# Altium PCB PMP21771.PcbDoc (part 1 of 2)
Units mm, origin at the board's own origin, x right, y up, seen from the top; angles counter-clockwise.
Board outline 125.73 x 87.63 mm, 4 copper layers (Top Layer, Signal Layer 1, Signal Layer 2, Bottom Layer), stack 2.225 mm thick; 58 components, 23 nets, 122 pads, 58 vias.
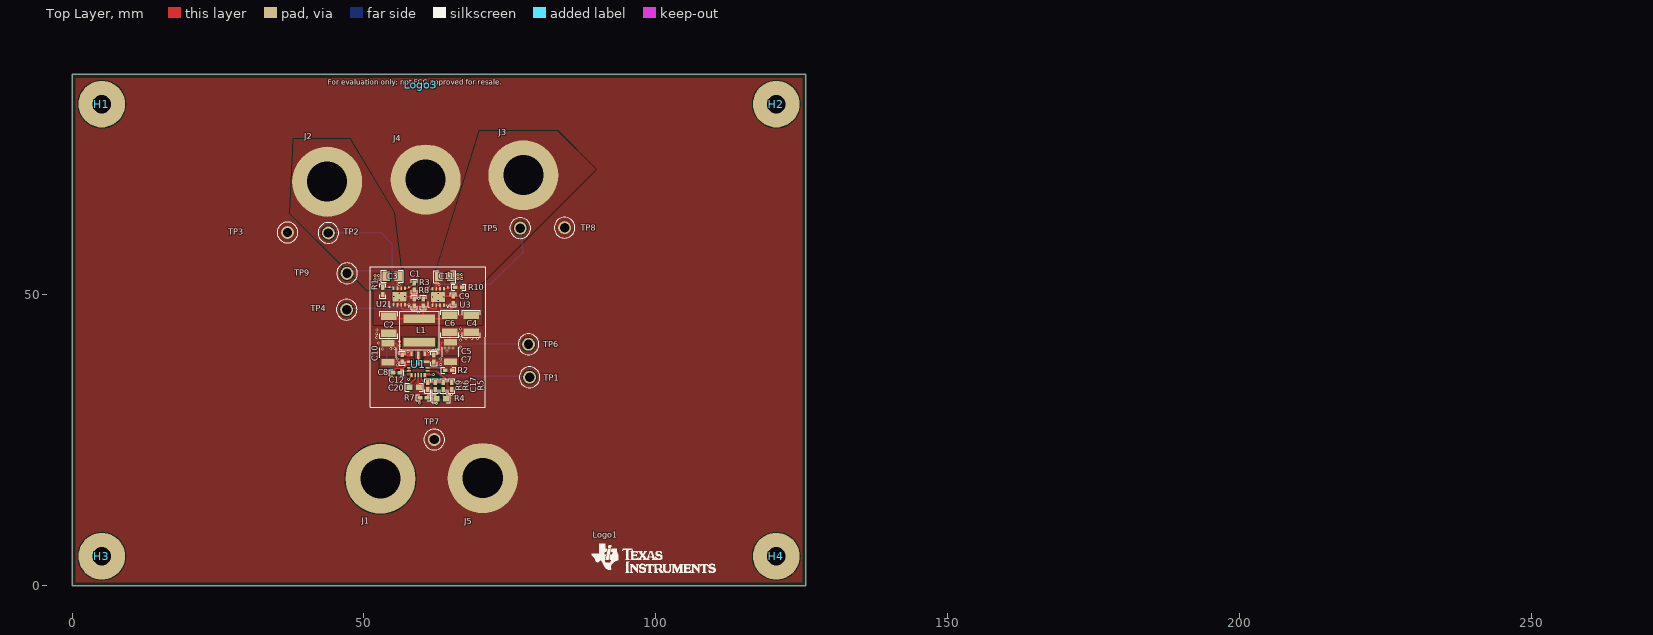
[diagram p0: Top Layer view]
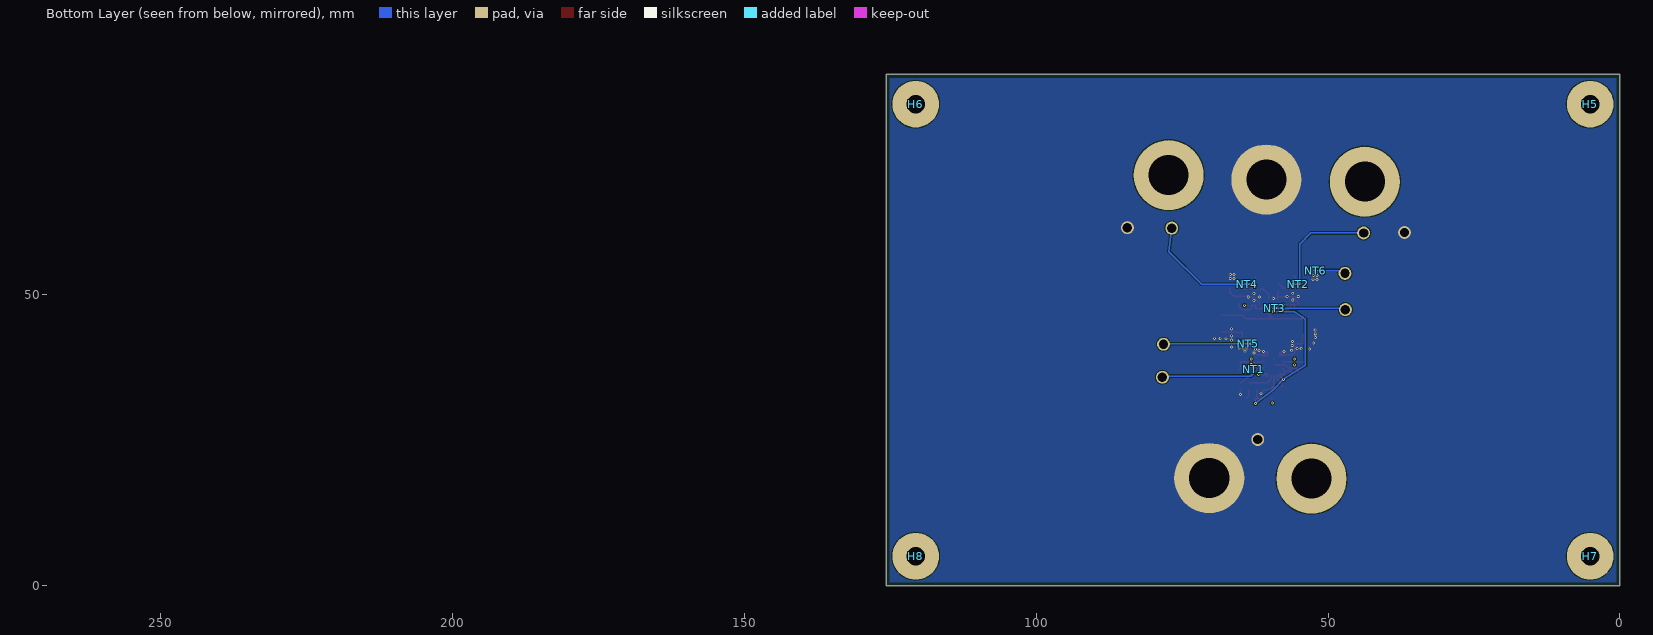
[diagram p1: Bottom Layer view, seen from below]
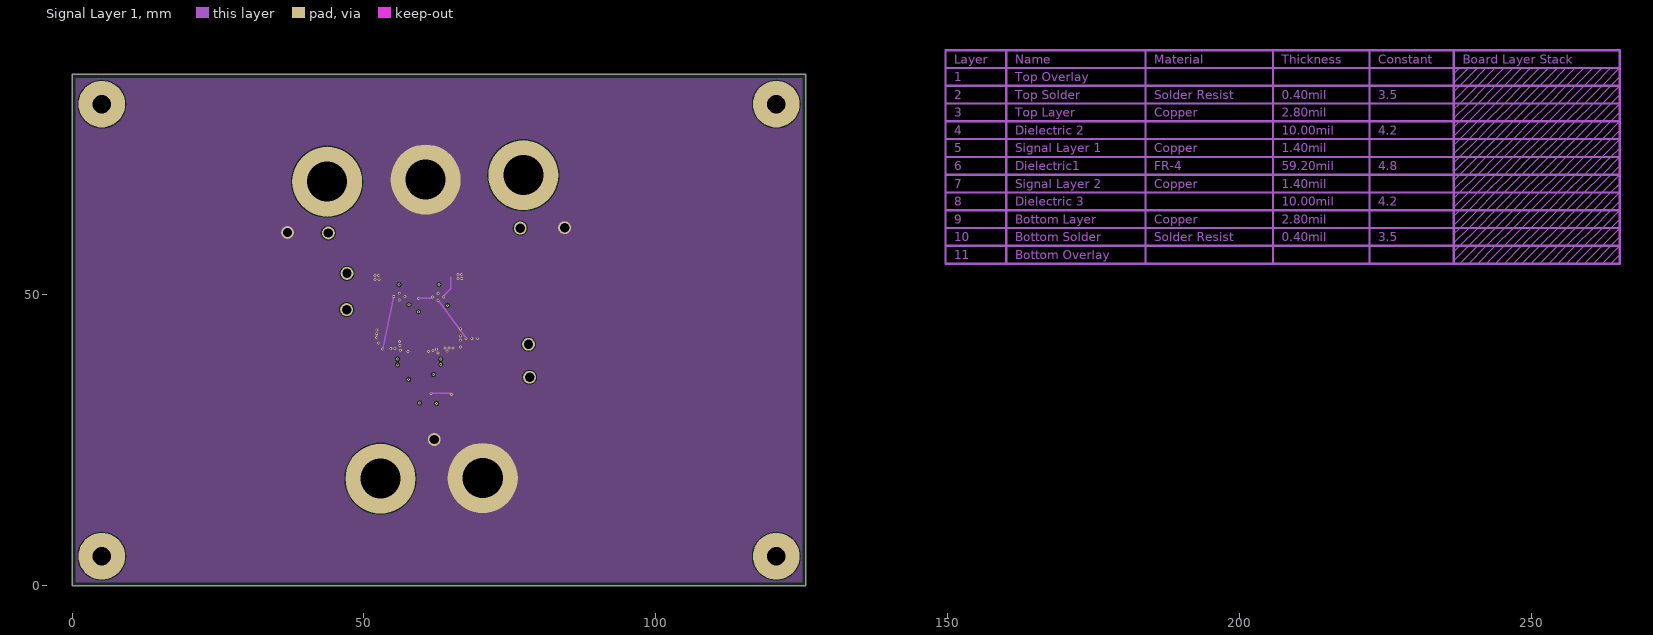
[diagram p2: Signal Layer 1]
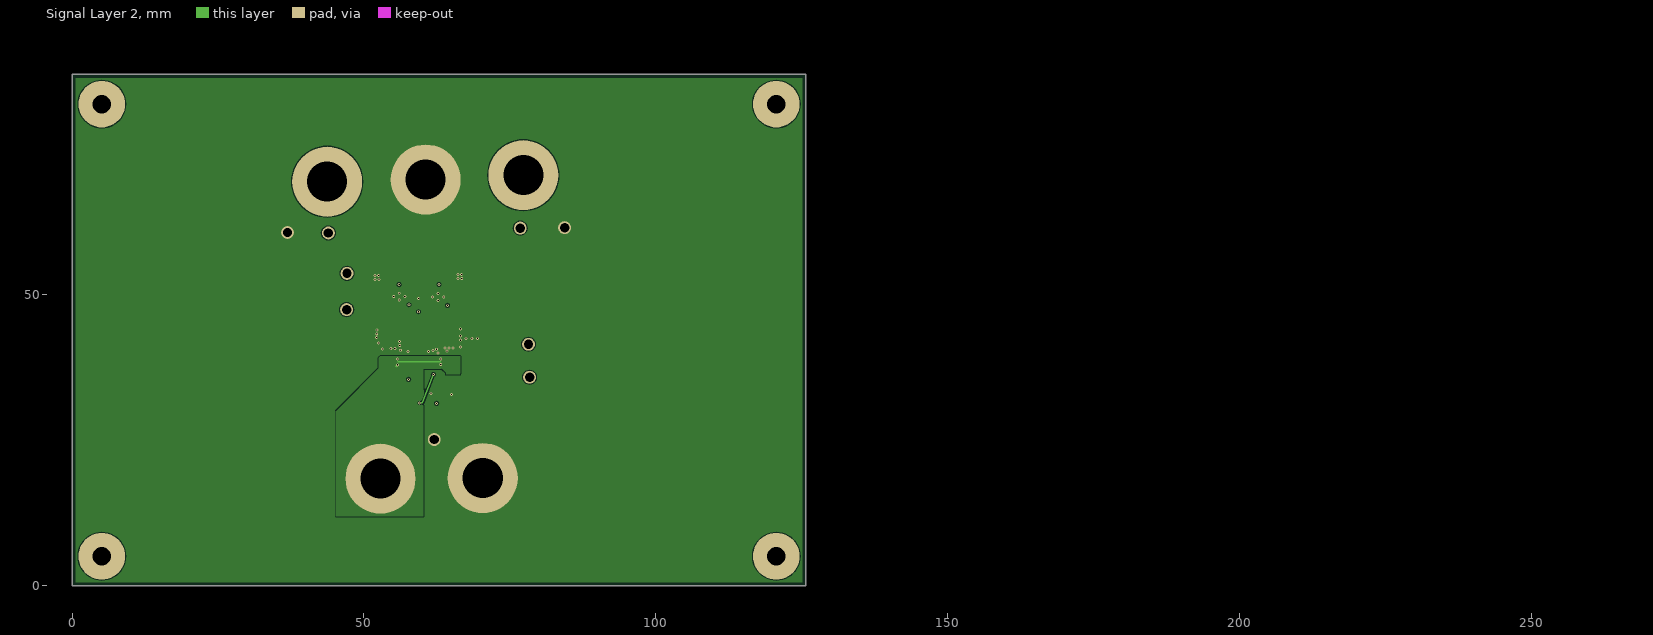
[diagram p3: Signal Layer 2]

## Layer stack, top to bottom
Top Solder: solder mask 0.0102, Solder Resist, Dk 3.5
Top Layer: signal copper 0.0711
Dielectric 2: dielectric 0.254, Dk 4.2
Signal Layer 1: signal copper 0.0356
Dielectric1: core 1.5037, FR-4, Dk 4.8
Signal Layer 2: signal copper 0.0356
Dielectric 3: dielectric 0.254, Dk 4.2
Bottom Layer: signal copper 0.0711
Bottom Solder: solder mask 0.0102, Solder Resist, Dk 3.5

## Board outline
0,0 125.73,0 125.73,87.63 0,87.63

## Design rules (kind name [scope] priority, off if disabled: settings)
AcuteAngle [All] p1: minimum=4.50000000000000E+0001 checktracksonly=FALSE
AssemblyTestPointUsage [All] p1: valid=2
BoardOutlineClearance BoardOutlineClearance_MountingHoles [OnCopper and InComponentClass('Mounting Holes')] p1: gap=0.635 ignorepadtopadclearanceinfootprint=FALSE
BoardOutlineClearance BoardOutlineClearance_Poly [OnCopper and InPoly] p2: gap=0.635 ignorepadtopadclearanceinfootprint=FALSE
BoardOutlineClearance [OnCopper and Not InComponentClass('Logo') and not InComponentClass('FiducialMark') and not InRegion(1000,500,4000,800)] p3: gap=0.635 ignorepadtopadclearanceinfootprint=FALSE
Clearance Clearance_Keepouts [((IsTrack Or IsArc) And Not InPoly) And IsFree and IsKeepOut vs ((IsTrack Or IsArc) And Not InPoly) And IsFree and IsKeepOut] p1: gap=0 ignorepadtopadclearanceinfootprint=FALSE
Clearance Clearance_Poly [InPolygon] p2: gap=0.152 ignorepadtopadclearanceinfootprint=FALSE
Clearance [All] p3: gap=0.2 ignorepadtopadclearanceinfootprint=FALSE except(0: Arc-Hole Track-Hole SMDPad-Hole THPad-Hole Via-Hole Fill-Hole Poly-Hole Region-Hole Text-Hole)
ComponentClearance ComponentClearance_MountingHoles_FiducialMarks [InComponentClass('Mounting Holes') vs InComponentClass('FiducialMark')] p1: gap=1.27 collisioncheckmode=3 verticalgap=0.254 showdistances=FALSE
ComponentClearance ComponentClearance_Shunt [InComponentClass('Header') vs InComponentClass('Shunt')] p2: gap=0 collisioncheckmode=3 verticalgap=0 showdistances=FALSE
ComponentClearance ComponentClearance_Logo [InComponentClass('Logo')] p3: gap=1.27 collisioncheckmode=3 verticalgap=0.254 showdistances=FALSE
ComponentClearance ComponentClearance_ScrewToNut [(HasFootprint('NY PMS 440 0025 PH')) vs (HasFootprint('Keystone_1902C'))] p4: gap=0.127 collisioncheckmode=3 verticalgap=0.254 showdistances=FALSE
ComponentClearance ComponentClearance_MountingHoles [InComponentClass('Mounting Holes')] p5: gap=6.35 collisioncheckmode=3 verticalgap=2540 showdistances=FALSE
ComponentClearance ComponentClearance_SmallPassives [HasFootprint('0201*') or HasFootprint('0402*') or HasFootprint('0508') or HasFootprint('0603*') or HasFootprint('0612') or HasFootprint('0805*') or HasFootprint('0815*') or HasFootprint('0830*') or HasFootprint('1206*') or HasFootprint('1210*') or HasFootprint('1808*') or HasFootprint('1812*') or HasFootprint('1825*') or HasFootprint('2010*') or HasFootprint('2220*') or HasFootprint('2225*') or HasFootprint('2512*') or HasFootprint('2728*') or HasFootprint('3518*') vs HasFootprint('0201*') or HasFootprint('0402*') or HasFootprint('0508') or HasFootprint('0603*') or HasFootprint('0612') or HasFootprint('0805*') or HasFootprint('0815*') or HasFootprint('0830*') or HasFootprint('1206*') or HasFootprint('1210*') or HasFootprint('1808*') or HasFootprint('1812*') or HasFootprint('1825*') or HasFootprint('2010*') or HasFootprint('2220*') or HasFootprint('2225*') or HasFootprint('2512*') or HasFootprint('2728*') or HasFootprint('3518*')] p6: gap=0.1 collisioncheckmode=3 verticalgap=0.254 showdistances=FALSE
ComponentClearance ComponentClearance_THtoSMT [IsThruComponent vs IsSMTComponent] p7: gap=0.381 collisioncheckmode=3 verticalgap=0.762 showdistances=FALSE
ComponentClearance ComponentClearance_THtoTH [IsThruComponent vs IsThruComponent] p8: gap=0.381 collisioncheckmode=3 verticalgap=0.762 showdistances=FALSE
ComponentClearance [All] p9: gap=0.1 collisioncheckmode=3 verticalgap=0.1 showdistances=FALSE
DiffPairsRouting [All] p1: maxlimit=2.54 minlimit=0.254 mostfreqgap=0.254 toplayer_minwidth=0.381 toplayer_maxwidth=0.381 toplayer_prefwidth=0.381 midlayer1_minwidth=0.381 midlayer1_maxwidth=0.381 midlayer1_prefwidth=0.381 midlayer2_minwidth=0.381 midlayer2_maxwidth=0.381 midlayer2_prefwidth=0.381 bottomlayer_minwidth=0.381 bottomlayer_maxwidth=0.381 bottomlayer_prefwidth=0.381 maxuncoupledlength=25.4
FabricationTestPointUsage TestPointUsage [All] p1: valid=2 allowmultiple=FALSE
FabricationTestpoint Testpoint [All] p1: side=3 testpointundercomponent=TRUE minsize=1.016 maxsize=2.54 preferedsize=1.524 minholesize=0 maxholesize=1.016 preferedholesize=0.813 testpointgrid=0.025 allowsidetop=TRUE allowsidebottom=TRUE usegrid=TRUE gridtolerance=0
FanoutControl Fanout_LCC [IsLCC] p1: bgadir=Out bgaviamode=Centered fanoutstyle=Auto fanoutdirection=Alternating viagrid=0.025 // Fanout_LCC (Default Rule)
FanoutControl Fanout_BGA [IsBGA] p2: bgadir=Out bgaviamode=Centered fanoutstyle=Auto fanoutdirection=Alternating viagrid=0.025 // Fanout_BGA (Default Rule)
FanoutControl Fanout_Default [All] p4: bgadir=Out bgaviamode=Centered fanoutstyle=Auto fanoutdirection=Alternating viagrid=0.025 // Fanout_Default (Default Rule)
FanoutControl Fanout_Small [(CompPinCount < 5)] p5: bgadir=Out bgaviamode=Centered fanoutstyle=Auto fanoutdirection=OutThenIn viagrid=0.025 // Fanout_Small (Default Rule)
HoleSize [All] p1: absolutevalues=TRUE maxlimit=6.375 minlimit=0.2 maxpercent=80.000 minpercent=20.000
MinimumAnnularRing MinimumAnnularRing_ThermalPadVias [IsVia and InAnyComponent] p1: minimumring=0.15
MinimumAnnularRing [All] p2: minimumring=0.203
MinimumSolderMaskSliver MinimumSolderMaskSliver_Logo [InComponentClass('Logo') vs InComponentClass('Logo')] p1: minsoldermaskwidth=0.018
MinimumSolderMaskSliver [All] p2: minsoldermaskwidth=0.1
PlaneConnect [All] p1: planeconnectstyle=Direct reliefexpansion=0.254 reliefentries=4 reliefconductorwidth=0.254 reliefairgap=0.254
PolygonConnect [All] p1: connectstyle=Direct reliefconductorwidth=0.254 reliefentries=4 polygonreliefangle="90 Angle" airgapwidth=0.254
RoutingLayers [All] p1: top layer_v5=TRUE mid layer 1_v5=FALSE mid layer 2_v5=FALSE bottom layer_v5=TRUE
RoutingVias ThermalPadVias [IsVia and InAnyComponent] p1: holewidth=0.2 width=0.5 viastyle="Through Hole" minholewidth=0.2 minwidth=0.5 maxholewidth=0.33 maxwidth=0.6
RoutingVias [All] p2: holewidth=0.406 width=0.864 viastyle="Through Hole" minholewidth=0.2 minwidth=0.66 maxholewidth=1.016 maxwidth=1.651
SilkToBoardRegionClearance [Not ((IsComment or IsDesignator) And (Hide <> 'False')) and not InRegion(1000,500,4000,800)] p1:
SilkToSilkClearance SilkToSilkClearance_Pb-FreeLogo [(HasFootprint('Pb-Free_Overlay_Medium') OR HasFootprint('Pb-Free_Overlay_Small')) vs (HasFootprint('Pb-Free_Overlay_Medium') OR HasFootprint('Pb-Free_Overlay_Small'))] p1: silktosilkclearance=0
SilkToSilkClearance [All] p2: silktosilkclearance=0.102
SilkToSolderMaskClearance SilkToComponentPadClearance [IsPad and InAnycomponent] p1: minsilkscreentomaskgap=0.127 clearancetoexposedcopper=TRUE
SilkToSolderMaskClearance "Silk to Solder Mask Opening" [All] p2: minsilkscreentomaskgap=0.102 clearancetoexposedcopper=FALSE
SolderMaskExpansion [All] p1: expansion=0.05
Width [All] p1: maxlimit=2.54 minlimit=0.152 preferedwidth=0.254 checkconnectedcopper=TRUE
14 further rules are at their usual default settings.

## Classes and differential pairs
component class PMP21771_Main: C1 C2 C3 C4 C5 C6 C7 C8 C9 C10 C11 C12 C17 C20 J1 J2 J3 J4 J5 L1 NT1 NT2 NT3 NT4 NT5 NT6 R1 R2 R3 R4 R5 R6 R7 R8 R9 R10 TP1 TP2 TP3 TP4 TP5 TP6 TP7 TP8 TP9 U1 U2 U3
component class "Mounting Holes": H1 H2 H3 H4
component class Logo: Logo1
component class PMP21771_Hardware: H1 H2 H3 H4 H5 H6 H7 H8 Logo1 Logo3

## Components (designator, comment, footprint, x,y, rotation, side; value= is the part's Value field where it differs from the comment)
C1 "C0402C104K4RACAUTO" 0402 58.598,48.555 r90 top value=0.1uF
C2 "GCM32ER70J476KE19L" 1210_270 54.25,44.724 r270 top value=47uF
C3 "JMJ212CB7106KGHT" 0805_HV 54.824,53.042 r180 top value=10uF
C4 "GCM32ER70J476KE19L" 1210_270 68.395,44.928 r270 top value=47uF
C5 "CGA6P3X7R1H475K250AB" 1210_280 64.826,40.075 r90 top value=4.7uF
C6 "GCM32ER70J476KE19L" 1210_270 64.702,44.928 r270 top value=47uF
C7 "CGA2B3X7R1H104K050BB" 0402 61.996,38.965 r90 top value=0.1uF
C8 "CGA2B3X7R1H104K050BB" 0402 56.576,39 r90 top value=0.1uF
C9 "C0402C104K4RACAUTO" 0402 65.33,49.021 r90 top value=0.1uF
C10 "CGA6P3X7R1H475K250AB" 1210_280 54.126,39.95 r90 top value=4.7uF
C11 "JMJ212CB7106KGHT" 0805_HV 63.825,53 r0 top value=10uF
C12 "C0402C104K4RACAUTO" 0402 55.575,36.55 r180 top value=0.1uF
C17 "C0402C330J5GACAUTO" 0402 63.559,34.25 r90 top value=33pF
C20 "GCM188R71C105KA64D" 0603 58.598,34.026 r0 top value=1uF
H1 "NY PMS 440 0025 PH" "NY PMS 440 0025 PH" 5.08,82.55 r0 top locked
H2 "NY PMS 440 0025 PH" "NY PMS 440 0025 PH" 120.65,82.55 r0 top locked
H3 "NY PMS 440 0025 PH" "NY PMS 440 0025 PH" 5.08,5.08 r0 top locked
H4 "NY PMS 440 0025 PH" "NY PMS 440 0025 PH" 120.65,5.08 r0 top locked
H5 "1902C" Keystone_1902C 5.08,82.55 r180 bottom locked
H6 "1902C" Keystone_1902C 120.65,82.55 r180 bottom locked
H7 "1902C" Keystone_1902C 5.08,5.08 r180 bottom locked
H8 "1902C" Keystone_1902C 120.65,5.08 r180 bottom locked
J1 "3267" Pomona_3267 52.825,18.375 r0 top
J2 "3267" Pomona_3267 43.7,69.25 r0 top
J3 "3267" Pomona_3267 77.3,70.375 r0 top
J4 "3267" Pomona_3267 60.578,69.625 r0 top
J5 "3267" Pomona_3267 70.35,18.475 r0 top
L1 "XAL6060-472MEB" XAL6060 59.476,43.777 r90 top value=4.7uH
Logo1 "Texas Instruments" TI_Stacked_Overlay_Small 99.623,4.75 r0 top
Logo3 "FCC disclaimer" FCC_disclaimer 59.69,85.852 r0 top
NT1 "Net-Tie" Net-Tie_10mil 62.715,37.146 r90 bottom net-tie
NT2 "Net-Tie" Net-Tie_10mil 55.082,51.65 r180 bottom net-tie
NT3 "Net-Tie" Net-Tie_10mil 59.146,47.575 r180 bottom net-tie
NT4 "Net-Tie" Net-Tie_10mil 63.869,51.675 r0 bottom net-tie
NT5 "Net-Tie" Net-Tie_10mil 63.663,41.5 r180 bottom net-tie
NT6 "Net-Tie" Net-Tie_10mil 52.139,54.04 r180 bottom net-tie
R1 "ERJ-2RKF1003X" 0402 53.23,50.529 r270 top value=100k
R2 "CRCW040244K2FKED" 0402 64.5,36.925 r0 top value=44.2k
R3 "CRCW040230K1FKED" 0402 58.58,51.287 r90 top value=30.1k
R4 "CRCW06031K00FKEA" 0603 63.243,32.062 r180 top value=1.00k
R5 "CRCW040239K2FKED" 0402 65,34.25 r90 top value=39.2k
R6 "RMCF0402FT100K" 0402 62.24,34.25 r270 top value=100k
R7 "CRCW040240R2FKED" 0402 60.2,32.232 r0 top value=40.2
R8 "ERJ-2RKF1003X" 0402 60.18,48.555 r270 top value=100k
R9 "CRCW040224K9FKED" 0402 60.92,34.25 r90 top value=24.9k
R10 "CRCW040230K1FKED" 0402 66.229,51.185 r180 top value=30.1k
TP1 "5129" Keystone5129 78.375,35.75 r0 top
TP2 "5129" Keystone5129 43.9,60.475 r0 top
TP3 "5011" Keystone5011 36.893,60.55 r0 top
TP4 "5129" Keystone5129 47.025,47.335 r0 top
TP5 "5129" Keystone5129 76.775,61.3 r0 top
TP6 "5129" Keystone5129 78.2,41.4 r0 top
TP7 "5011" Keystone5011 62.039,25.075 r0 top
TP8 "5011" Keystone5011 84.375,61.375 r0 top
TP9 "5011" Keystone5011 47.1,53.55 r0 top
U1 "LM61460AANQRJRTQ1" RJR0014A 59.286,37.965 r90 top
U2 "TPS2557QDRBRQ1" DRB0008B 56.046,49.571 r90 top
U3 "TPS2557QDRBRQ1" DRB0008B 62.715,49.5 r90 top

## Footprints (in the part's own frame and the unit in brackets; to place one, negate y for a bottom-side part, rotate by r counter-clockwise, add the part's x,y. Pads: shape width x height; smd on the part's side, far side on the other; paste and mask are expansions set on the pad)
0402 [mm] "0402 from SM-752 data"
  rect 0.8x0.6 smd: 1(-0.6,0) 2(0.6,0)
  silkscreen extent -1.22,-0.52 1.22,0.52, body extent -0.55,-0.3 0.55,0.3, height 0.6
0603 [mm] "0603 from SM-752 data"
  rect 1x0.95 smd: 1(-0.8,0) 2(0.8,0)
  silkscreen extent -1.52,-0.69 1.52,0.69, body extent -0.87,-0.47 0.87,0.47, height 1
0805_HV [mil] "0805 with 30mil clearance between pads"
  rect 50x63 smd: 1(-40,0) 2(40,0)
  silkscreen extent -74,-40 74,40, body extent -43,-29 43,29, height 57
1210_270 [mm] "1210"
  rect 1.3x2.7 smd: 1(-1.45,0) 2(1.45,0)
  silkscreen extent -2.32,-1.57 2.32,1.57, body extent -1.7,-1.35 1.7,1.35, height 2.7
1210_280 [mm] "SMD, 2-Leads, Body 3.6x2.8mm, Height 2.8mm"
  rect 1.1x2.2 smd: 1(-1.65,0) 2(1.65,0)
  silkscreen extent -0.84,-1.4 0.84,1.4, body extent -1.8,-1.4 1.8,1.4, height 2.8
DRB0008B [mm] "SON, 8-Leads, Body 3x3mm, Pitch 0.65mm, Thermal Pad 2.4x1.65mm, TI Recommended"
  rrect33% 0.6x0.3 smd: 1(-1.4,0.975) 2(-1.4,0.325) 3(-1.4,-0.325) 4(-1.4,-0.975) 5(1.4,-0.975) 6(1.4,-0.325) 7(1.4,0.325) 8(1.4,0.975)
  rrect9% 1.47x1.06 on Top Paste: 9(0,0.63) 9(0,-0.63)
  rrect6% 1.65x2.4 smd paste-1.2: 9(0,0)
  silkscreen extent -1.73,-1.73 1.73,1.73, body extent -1.5,-1.5 1.5,1.5, height 0.96
FCC_disclaimer [mm]
Keystone5011 [mil] "Keystone Multipurpose loops"
  round 87 hole 63: 1(0,0)
  silkscreen extent -70,-70 70,70, body extent -63,-63 63,62, height 319
Keystone5129 [mil] "Keystone Multipurpose loops"
  round 87 hole 63: 1(0,0)
  silkscreen extent -70,-70 70,70, body extent -63,-63 63,62, height 319
Keystone_1902C [mil] "Hex Standoff, 4-40 threaded, nylon"
  round 1 on Mech4: 0(0,0)
  body extent -145,-126 146,126, height 501
Net-Tie_10mil [mil] "10mil net tie, no solder mask opening, no solder paste"
  rect 10x10 smd paste-5 mask-5: 1(-10,0) 2(10,0)
  Top Layer region: -6,5 6,5 6,-5 -6,-5
"NY PMS 440 0025 PH" [mm] "4-40 nylon screw and mounting hole"
  round 8 hole 3.2: 1(0,0)
  body extent -3.3,-3.3 3.3,3.3, height 2.69
Pomona_3267 [mm] "Standard Uninsulated Banana Jack"
  round 12 hole 6.858: 1(0,0)
  body extent -4.12,-4.82 4.26,4.85, height 2.79
RJR0014A [mm] "VQFN-HR-14"
  rrect25% 0.7x0.4 smd paste-0.3: 1(-1.85,1.15) 5(-1.85,-1.15)
  rrect40% 0.7x0.25 smd: 2(-1.85,0.525) 4(-1.85,-0.525)
  rrect33% 0.7x0.3 smd: 3(-1.85,0)
  rrect40% 0.25x0.7 smd: 6(-1.125,-1.6) 7(-0.625,-1.6) 13(-0.625,1.6) 14(-1.125,1.6)
  rrect25% 0.4x1 smd: 8(0.45,-1.45) 12(0.45,1.45)
  rrect25% 0.8x0.4 smd paste-0.3: 9(1.8,-1.15) 11(1.8,1.15)
  rrect25% 1.1x0.4 on Top Paste: 10(0.35,0) 10(1.65,0)
  rrect25% 2.4x0.4 smd paste-0.3: 10(1,0)
  Top Layer region: -2.2,1 -2.2,1.3 -2.196,1.319 -2.185,1.335 -2.169,1.346 -2.15,1.35 -2.15,1.35 -2.15,1.35 -1.97,1.35 -1.924,1.359 -1.885,1.385 -1.859,1.424 -1.85,1.47 -1.85,1.47 -1.85,1.9 -1.85,1.9 -1.846,1.919 -1.835,1.935 -1.819,1.946 -1.8,1.95 -1.8,1.95 -1.55,1.95 -1.531,1.946 -1.515,1.935 -1.504,1.919 -1.5,1.9 -1.5,1.9 -1.5,1 -1.504,0.981 -1.515,0.965 -1.531,0.954 -1.55,0.95 -1.55,0.95 -2.15,0.95 -2.169,0.954 -2.185,0.965 -2.196,0.981 -2.2,1
  Top Layer region: 1.4,1 1.4,1.9 1.404,1.919 1.415,1.935 1.431,1.946 1.45,1.95 1.45,1.95 1.75,1.95 1.769,1.946 1.785,1.935 1.796,1.919 1.8,1.9 1.8,1.9 1.8,1.47 1.809,1.424 1.835,1.385 1.874,1.359 1.92,1.35 1.92,1.35 2.15,1.35 2.15,1.35 2.169,1.346 2.185,1.335 2.196,1.319 2.2,1.3 2.2,1.3 2.2,1 2.196,0.981 2.185,0.965 2.169,0.954 2.15,0.95 2.15,0.95 1.45,0.95 1.431,0.954 1.415,0.965 1.404,0.981 1.4,1
  Top Layer region: 1.4,-1.9 1.404,-1.919 1.415,-1.935 1.431,-1.946 1.45,-1.95 1.45,-1.95 1.75,-1.95 1.769,-1.946 1.785,-1.935 1.796,-1.919 1.8,-1.9 1.8,-1.9 1.8,-1.47 1.809,-1.424 1.835,-1.385 1.874,-1.359 1.92,-1.35 1.92,-1.35 2.15,-1.35 2.169,-1.346 2.185,-1.335 2.196,-1.319 2.2,-1.3 2.2,-1.3 2.2,-1 2.196,-0.981 2.185,-0.965 2.169,-0.954 2.15,-0.95 2.15,-0.95 1.45,-0.95 1.431,-0.954 1.415,-0.965 1.404,-0.981 1.4,-1 1.4,-1
  Top Layer region: -2.15,-1.35 -2.169,-1.346 -2.185,-1.335 -2.196,-1.319 -2.2,-1.3 -2.2,-1.3 -2.2,-1 -2.196,-0.981 -2.185,-0.965 -2.169,-0.954 -2.15,-0.95 -2.15,-0.95 -1.55,-0.95 -1.531,-0.954 -1.515,-0.965 -1.504,-0.981 -1.5,-1 -1.5,-1 -1.5,-1.9 -1.504,-1.919 -1.515,-1.935 -1.531,-1.946 -1.55,-1.95 -1.55,-1.95 -1.8,-1.95 -1.819,-1.946 -1.835,-1.935 -1.846,-1.919 -1.85,-1.9 -1.85,-1.9 -1.85,-1.9 -1.85,-1.47 -1.859,-1.424 -1.885,-1.385 -1.924,-1.359 -1.97,-1.35 -1.97,-1.35
  body extent -2,-1.75 2,1.75, height 1
TI_Stacked_Overlay_Small [mm]
  silkscreen extent -10.63,-2.49 10.63,2.49
XAL6060 [mil] "Coilcraft recommended land pattern Document 887-4 Revised 11/20/12"
  rect 56x210 smd: 1(-79.5,0) 2(79.5,0)
  silkscreen extent -129,-133 129,133, body extent -129,-133 129,133, height 240

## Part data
C1 C9: library part CMP-0006237-2, "CAP, CERM, 0.1 uF, 16 V, +/- 10%, X7R, AEC-Q200 Grade 1, 0402", Cap_Case=0402, Manufacturer=Kemet, Supplier Part Number 1=399-6828-1-ND, TempCo=X7R, Tolerance_%=10%, Value1=Unknown, Value2=16V, ValueDisplayed=0.1uF
C2 C4 C6: library part CMP-0009172-1, "CAP, CERM, 47 uF, 6.3 V, +/- 10%, X7R, AEC-Q200 Grade 1, 1210", Cap_Case=1210, Manufacturer=MuRata, Supplier Part Number 1=490-4844-1-ND, TempCo=X7R, Tolerance_%=10%, Value1=Unknown, Value2=6.3V, ValueDisplayed=47uF
C3 C11: library part CMP-0081188-1, "CAP, CERM, 10 µF, 6.3 V,+/- 10%, X7R, AEC-Q200 Grade 1, 0805", Cap_Case=0805, Manufacturer="Taiyo Yuden", Supplier Part Number 1=587-4357-1-ND, TempCo=X7R, Tolerance_%=10%, Value2=6.3V, ValueDisplayed=10µF
C5 C10: library part CMP-0009162-1, "CAP, CERM, 4.7 uF, 50 V, +/- 10%, X7R, AEC-Q200 Grade 1, 1210", Cap_Case=1210_280, Manufacturer=TDK, Supplier Part Number 1=445-6999-1-ND, TempCo=X7R, Tolerance_%=10%, Value1="0.003166 ohm", Value2=50V, ValueDisplayed=4.7uF
C7: library part CMP-0006325-1, "CAP, CERM, 0.1 uF, 50 V, +/- 10%, X7R, AEC-Q200 Grade 1, 0402", Cap_Case=0402, Manufacturer=TDK, Supplier Part Number 1=445-6899-1-ND, TempCo=X7R, Tolerance_%=10%, Value1="0.039064 ohm", Value2=50V, ValueDisplayed=0.1uF
C8: library part CMP-0006325-2, "CAP, CERM, 0.1 uF, 50 V, +/- 10%, X7R, AEC-Q200 Grade 1, 0402", Cap_Case=0402, Manufacturer=TDK, Supplier Part Number 1=445-6899-1-ND, TempCo=X7R, Tolerance_%=10%, Value1="0.039064 ohm", Value2=50V, ValueDisplayed=0.1uF
C12: library part CMP-0006237-1, "CAP, CERM, 0.1 uF, 16 V, +/- 10%, X7R, AEC-Q200 Grade 1, 0402", Cap_Case=0402, Manufacturer=Kemet, Supplier Part Number 1=399-6828-1-ND, TempCo=X7R, Tolerance_%=10%, Value1=Unknown, Value2=16V, ValueDisplayed=0.1uF
C17: library part CMP-0079151-1, "CAP, CERM, 33 pF, 50 V,+/- 5%, C0G, AEC-Q200 Grade 1, 0402", Cap_Case=0402, Manufacturer=Kemet, Supplier Part Number 1=399-12979-1-ND, TempCo=C0G, Tolerance_%=5%, Value2=50V, ValueDisplayed=33pF
C20: library part CMP-0007136-1, "CAP, CERM, 1 uF, 16 V, +/- 10%, X7R, AEC-Q200 Grade 1, 0603", Cap_Case=0603, Manufacturer=MuRata, Supplier Part Number 1=490-5241-6-ND, TempCo=X7R, Tolerance_%=10%, Value1=Unknown, Value2=16V, ValueDisplayed=1uF
H1 H2 H3 H4: library part CMP-0003617-1, "Machine Screw, Round, #4-40 x 1/4, Nylon, Philips panhead", Manufacturer="B&F Fastener Supply", Supplier Part Number 1=H542-ND
H5 H6 H7 H8: library part CMP-0003610-1, "Standoff, Hex, 0.5\"L #4-40 Nylon", Manufacturer=Keystone, Supplier Part Number 1=36-1902C-ND
J1 J2 J3 J4 J5: library part CMP-0055388-2, "Standard Banana Jack, Uninsulated", Manufacturer="Pomona Electronics", Supplier Part Number 1=501-1115-ND
L1: library part CMP-0061020-1, "Inductor, Shielded, Composite, 4.7 uH, 10.5 A, 0.015 ohm, SMD", Manufacturer=Coilcraft, Value1="0.015 ohm", Value2=10.5A, ValueDisplayed=4.7uH
Logo1: library part CMP-0074838-1, "Texas Instrument Corporate Signature"
Logo3: library part CMP-0074847-1, "FCC_disclaimer"
NT1 NT2 NT3 NT4 NT5 NT6: library part CMP-0078142-1, "Single point connection between nets.", Manufacturer=N/A
R1 R8: library part CMP-0026659-1, "RES, 100 k, 1%, 0.1 W, 0402", Manufacturer=Panasonic, Power_W=100mW, TempCo="100 ppm/C", Tolerance_%=1%, Value2=0.1W, Value_Code=100k
R2: library part CMP-0026383-2, "RES, 44.2 k, 1%, 0.063 W, AEC-Q200 Grade 0, 0402", Manufacturer=Vishay-Dale, Power_W=63mW, Supplier Part Number 1=541-44.2KLCT-ND, TempCo="100 ppm/C", Tolerance_%=1%, Value2=0.063W, Value_Code=44k2, ValueDisplayed=44.2k
R3 R10: library part CMP-0026284-2, "RES, 30.1 k, 1%, 0.063 W, AEC-Q200 Grade 0, 0402", Manufacturer=Vishay-Dale, Power_W=63mW, Supplier Part Number 1=541-30.1KLCT-ND, TempCo="100 ppm/C", Tolerance_%=1%, Value2=0.063W, Value_Code=30k1, ValueDisplayed=30.1k
R4: library part CMP-0022109-5, "RES, 1.00 k, 1%, 0.1 W, AEC-Q200 Grade 0, 0603", Manufacturer=Vishay-Dale, Power_W=100mW, Supplier Part Number 1=541-1.00KHCT-ND, TempCo="100 ppm/C", Tolerance_%=1%, Value2=0.1W, Value_Code=1k00, ValueDisplayed=1.00k
R5: library part CMP-0026327-2, "RES, 39.2 k, 1%, 0.063 W, AEC-Q200 Grade 0, 0402", Manufacturer=Vishay-Dale, Power_W=63mW, Supplier Part Number 1=541-39.2KLCT-ND, TempCo="100 ppm/C", Tolerance_%=1%, Value2=0.063W, Value_Code=39k2, ValueDisplayed=39.2k
R6: library part CMP-0026753-1, "RES, 100 k, 1%, 0.063 W, AEC-Q200 Grade 0, 0402", Manufacturer="Stackpole Electronics Inc", Power_W=63mW, Supplier Part Number 1=RMCF0402FT100KCT-ND, TempCo="100 ppm/C", Tolerance_%=1%, Value2=0.063W, Value_Code=100k
R7: library part CMP-0026368-2, "RES, 40.2, 1%, 0.063 W, AEC-Q200 Grade 0, 0402", Manufacturer=Vishay-Dale, Power_W=63mW, Supplier Part Number 1=541-40.2LCT-ND, TempCo="100 ppm/C", Tolerance_%=1%, Value2=0.063W, Value_Code=40R2, ValueDisplayed=40.2
R9: library part CMP-0026196-2, "RES, 24.9 k, 1%, 0.063 W, AEC-Q200 Grade 0, 0402", Manufacturer=Vishay-Dale, Power_W=63mW, Supplier Part Number 1=541-24.9KLCT-ND, TempCo="100 ppm/C", Tolerance_%=1%, Value2=0.063W, Value_Code=24k9, ValueDisplayed=24.9k
TP1 TP2 TP4 TP5 TP6: library part CMP-0055160-1, "Test Point, Multipurpose, Purple, TH", Color=Purple, Manufacturer=Keystone, Supplier Part Number 1=36-5129-ND
TP3 TP7 TP8 TP9: library part CMP-0055148-1, "Test Point, Multipurpose, Black, TH", Color=Black, Manufacturer=Keystone, Supplier Part Number 1=36-5011-ND
U1: library part CMP-0079820-1, "Automotive 6-A Low Noise Synchronous Buck Regulators, RJR0014A (VQFN-HR-14)", Alternate Manufacturer="Texas Instruments"
U2 U3: library part CMP-0074282-3, "PRECISION ADJUSTABLE CURRENT-LIMITED POWER-DISTRIBUTION SWITCHES, DRB0008B (VSON-8)", Alternate Manufacturer="Texas Instruments", Alternate PartNumber=TPS2557QDRBTQ1

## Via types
v1: diameter 0.508, hole 0.203, Top Layer to Bottom Layer, 50 vias
v2: diameter 0.5, hole 0.2, Top Layer to Bottom Layer, 8 vias

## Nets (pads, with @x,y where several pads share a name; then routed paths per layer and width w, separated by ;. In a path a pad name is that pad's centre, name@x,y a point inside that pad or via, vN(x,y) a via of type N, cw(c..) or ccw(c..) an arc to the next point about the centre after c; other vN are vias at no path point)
EN/SYNC: R2.1 U1.7 | length 3.2
  Top Layer w0.254: U1.7@60.886,37.34 63.485,37.34 R2.1@63.9,36.925
FAULT1: R1.1 U2.8 | length 1.9
  Top Layer w0.254: R1.1@53.23,51.129 54.913,51.129 U2.8@55.071,50.971
FAULT2: R8.1 U3.8 | length 2.7
  Top Layer w0.254: R8.1@60.18,49.155 60.18,49.965 61.06,50.845 U3.8@61.685,50.845
FB: C17.2 R6.1 R9.2 U1.4 | length 4.7
  Top Layer w0.254: U1.4@59.811,36.115 59.811,35.414 60.375,34.85 R9.2@60.92,34.85 R6.1@62.24,34.85 C17.2@63.559,34.85
GND: C1.2 C2.2 C3.2 C4.2 C5.2 C6.2 C7.2 C8.2 C9.2 C10.2 C11.2 C20.2 J4.1 J5.1 NT5.2 NT6.1 R3.1 R5.1 R9.1 R10.1 TP3.1 TP7.1 TP8.1 U1.3 U1.9 U1.11 U2.1 U2.9@56.046,49.571 U3.1 U3.9@62.715,49.5 | length 66.7
  Top Layer w0.254: C10.2@54.126,41.6 54.25,41.724 C2.2@54.25,43.274 ; C10.2@54.236,41.488 55.486,41.488 55.721,41.254 55.721,39.965 56.086,39.6 C8.2@56.576,39.6 57.971,39.6 U1.11@58.136,39.765 ; U2.9@54.954,49.571 U2.9@56.046,49.571 ; U2.1@55.071,48.171 55.071,48.596 U2.9@56.046,49.571 ; R3.1@58.58,50.687 58.58,49.57 ; U1.3@59.286,36.115 59.286,34.139 C20.2@59.398,34.026 59.774,33.65 R9.1@60.92,33.65 61.47,33.1 v1(61.47,33) ; v1(59.375,49.25) 58.975,49.25 58.88,49.155 C1.2@58.598,49.155 58.58,49.172 58.58,49.57 ; 60.688,39.6 C7.2@61.996,39.6 ; U3.1@61.74,48.1 61.74,48.525 U3.9@62.715,49.5 U3.9@63.479,49.5 ; C7.2@61.996,39.323 63.259,40.587 63.259,41.608 63.376,41.725 C5.2@64.826,41.725 64.702,41.849 C6.2@64.702,43.478 C4.2@68.395,43.478 ; U3.9@63.665,49.621 C9.2@65.33,49.621 66.146,49.621 66.8,50.275 66.8,51.156 R10.1@66.829,51.185 ; v1(65,32.775) R5.1@65,33.65 ; U2.9@56.046,49.571 58.579,49.571 58.58,49.57
  Signal Layer 1 w0.254: v1(53.2,40.575) v2(55.096,49.571) ; v1(59.375,49.25) 61.515,49.25 v2(61.765,49.5) ; v1(61.47,33) 64.775,33 v1(65,32.775) ; v2(62.715,48.925) v1(67.5,42.425) ; v2@63.479,49.5 63.555,49.591 64.875,50.911 64.875,52.975
  Bottom Layer w0.254: 62.875,41.575 62.95,41.5 NT5.2@63.409,41.5
  other v1: 62.7,39.9 57.55,40.15 61.05,40.175 64.2,40.219 61.801,40.325 56.225,40.373 62.441,40.55 54.6,40.648 55.275,40.65 63.886,40.739 64.55,40.749 65.225,40.749 66.537,40.91 56.126,41.175 52.518,41.608 56.086,41.875 66.554,42.1 68.475,42.425 69.45,42.425 52.175,42.55 66.55,42.85 52.189,43.2 52.193,43.85 66.55,44.05 51.9,52.525 52.561,52.537 66.1,52.65 66.748,52.65 51.9,53.176 52.518,53.176 66.1,53.35 66.744,53.35
  other v2: 56.046,48.996 63.665,49.5 56.996,49.571 62.715,50.075 56.046,50.146
NetC12_1: C12.1 U1.13 U1.14 | length 2.2
  Top Layer w0.254: C12.1@56.175,36.55 56.421,36.796 57.686,36.796 U1.14@57.686,36.84 U1.13@57.686,37.34
NetC17_1: C17.1 R4.1 | length 1.8
  Top Layer w0.254: C17.1@63.559,33.65 63.559,32.545 R4.1@64.043,32.062
NetNT1_1: NT1.1 TP1.1 | length 16.4
  Bottom Layer w0.254: NT1.1@62.715,36.892 62.715,36.436 63.2,35.95 78.175,35.95 TP1.1@78.375,35.75
NetNT2_2: NT2.2 TP2.1 | length 18.6
  Bottom Layer w0.254: TP2.1@43.9,60.475 52.933,60.475 54.828,58.58 NT2.2@54.828,51.65
NetNT3_2: NT3.2 TP4.1 | length 12
  Bottom Layer w0.254: TP4.1@47.025,47.335 47.265,47.575 NT3.2@58.892,47.575
NetNT4_2: NT4.2 TP5.1 | length 19.7
  Bottom Layer w0.254: NT4.2@64.123,51.675 71.66,51.675 77.276,57.291 TP5.1@76.772,61.287 ; TP5.1@77.276,60.976 TP5.1@77.425,61.125
NetNT5_1: NT5.1 TP6.1 | length 14.3
  Bottom Layer w0.254: NT5.1@63.917,41.5 78.1,41.5 TP6.1@78.2,41.4
NetNT6_2: NT6.2 TP9.1 | length 5
  Bottom Layer w0.254: TP9.1@47.1,53.55 47.59,54.04 NT6.2@51.885,54.04
NetR3_2: R3.2 U2.5 | length 1.9
  Top Layer w0.254: U2.5@57.021,50.971 57.664,50.971 R3.2@58.58,51.887
NetR7_1: R7.1 U1.5 | length 7.9
  Top Layer w0.254: v1(59.55,31.325) 59.6,31.375 R7.1@59.6,32.232 ; U1.5@60.436,36.115 U1.5@60.436,36.251 ; 60.756,36.165 61.83,36.165 v1(61.875,36.21)
  Signal Layer 2 w0.254: v1(59.55,31.325) 59.575,31.35 60.025,31.35 v1@61.875,36.191
NetR10_2: R10.2 U3.5 | length 2.1
  Top Layer w0.254: U3.5@63.718,50.871 U3.5@63.69,50.9 64.5,50.9 64.785,51.185 R10.2@65.629,51.185
OUT1: C3.1 J2.1 NT2.1 U2.6 U2.7 | length 9.2
  Top Layer w0.254: J2.1@43.7,67.85 J2.1@43.7,69.25 J2.1@46.529,66.421 ; C3.1@55.625,53.258 C3.1@55.84,53.042 ; C3.1@55.673,53.042 55.673,51.019 U2.7@55.721,50.971 U2.6@56.371,50.971
  Bottom Layer w0.254: NT2.1@55.336,51.65 56.009,51.65 v1(56.034,51.625)
OUT2: C11.1 J3.1 NT4.1 U3.6 U3.7 | length 4
  Top Layer w0.254: C11.1@62.376,53 62.377,52.997 U3.7@62.39,50.9 U3.6@63.04,50.9 ; J3.1@77.3,69.875 J3.1@77.3,70.375
  Bottom Layer w0.254: v1(62.857,51.637) 62.895,51.675 NT4.1@63.615,51.675
RT: R5.2 U1.6 | length 4.8
  Top Layer w0.254: U1.6@60.886,36.84 62.39,36.796 64.975,34.823 R5.2@65,34.799
SW: C12.2 L1.1 U1.10@59.286,38.965 | length 4.9
  Top Layer w0.254: C12.2@54.996,36.771 55.475,37.25 56.711,37.25 56.711,37.273 57.32,37.883 U1.10@59.153,37.883 ; U1.10@59.286,38.732 U1.10@59.286,38.965
VCC: C20.1 U1.2 | length 2.5
  Top Layer w0.254: C20.1@57.798,34.026 57.798,34.548 58.761,35.511 U1.2@58.761,36.115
